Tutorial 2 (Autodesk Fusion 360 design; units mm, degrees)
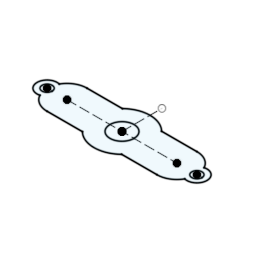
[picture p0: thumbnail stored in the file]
sketch "Sketch2" plane through (0, 0, 0) normal (0, 0, 1) x axis (1, 0, 0)
  line L1 (275, 0) -> (-275, 0)
  line L2 (0, 200) -> (0, 0)
  line L3 (-97.9796, -100) -> (-275, -100)
  line L4 (275, -100) -> (97.9796, -100)
  line L5 (97.9796, 100) -> (275, 100)
  line L6 (-275, 100) -> (-97.9796, 100)
  circle C1 centre (0, 0) radius 60
  circle C2 centre (375, 0) radius 25
  circle C3 centre (-375, 0) radius 25
  arc A1 centre (0, 0) radius 140 clockwise from (97.9796, -100) to (-97.9796, -100)
  arc A2 centre (0, 0) radius 140 clockwise from (-97.9796, 100) to (97.9796, 100)
  arc A3 centre (-375, 0) radius 50 clockwise from (-362.5, -48.4123) to (-362.5, 48.4123)
  arc A4 centre (375, 0) radius 50 clockwise from (362.5, 48.4123) to (362.5, -48.4123)
  arc A5 centre (-275, 0) radius 100 clockwise from (-362.5, 48.4123) to (-275, 100)
  arc A6 centre (-275, 0) radius 100 clockwise from (-275, -100) to (-362.5, -48.4123)
  arc A7 centre (275, 0) radius 100 clockwise from (362.5, -48.4123) to (275, -100)
  arc A8 centre (275, 0) radius 100 clockwise from (275, 100) to (362.5, 48.4123)
  point P1 (0, 0)
  point P2 (0, 0)
  point P10 (0, 0)
  point P3 (0, 0)
  point P15 (0, 0)
  point P19 (97.9796, 100)
  point P22 (-362.5, -48.4123)
  point P24 (362.5, 48.4123)
  point P13 (-375, 0)
  point P11 (375, 0)
  point P12 (375, 0)
  point P14 (-375, 0)
  point P26 (-275, 0)
  point P27 (275, 0)
  coincident P1 P2
  concentric C1 A1
  tangent L3 A7
  tangent L5 A7
  parallel L3 L5
  tangent L5 A5
  tangent L3 A5
  horizontal L1
  coincident P1 P10
  midpoint L1 P10
  concentric C2 A4
  concentric C3 A3
  coincident P3 P15
  perpendicular L1 L2
  collinear L3 L4
  coincident P19 A1
  collinear L5 L6
  concentric A1 A2
  coincident P22 A5
  coincident P24 A7
  concentric A5 A6
  coincident P13 A5
  concentric A7 A8
  coincident P11 A7
  equal C2 C3
  equal A3 A4
  symmetric P12 P14 L2
  dimension "d1" diameter C1 = 120
  dimension "d2" diameter C2 = 50
  dimension "d3" radius A2 = 140
  dimension "d4" radius A4 = 50
  dimension "d5" distance P26 P27 = 550
  dimension "d6" distance P12 P14 = 750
